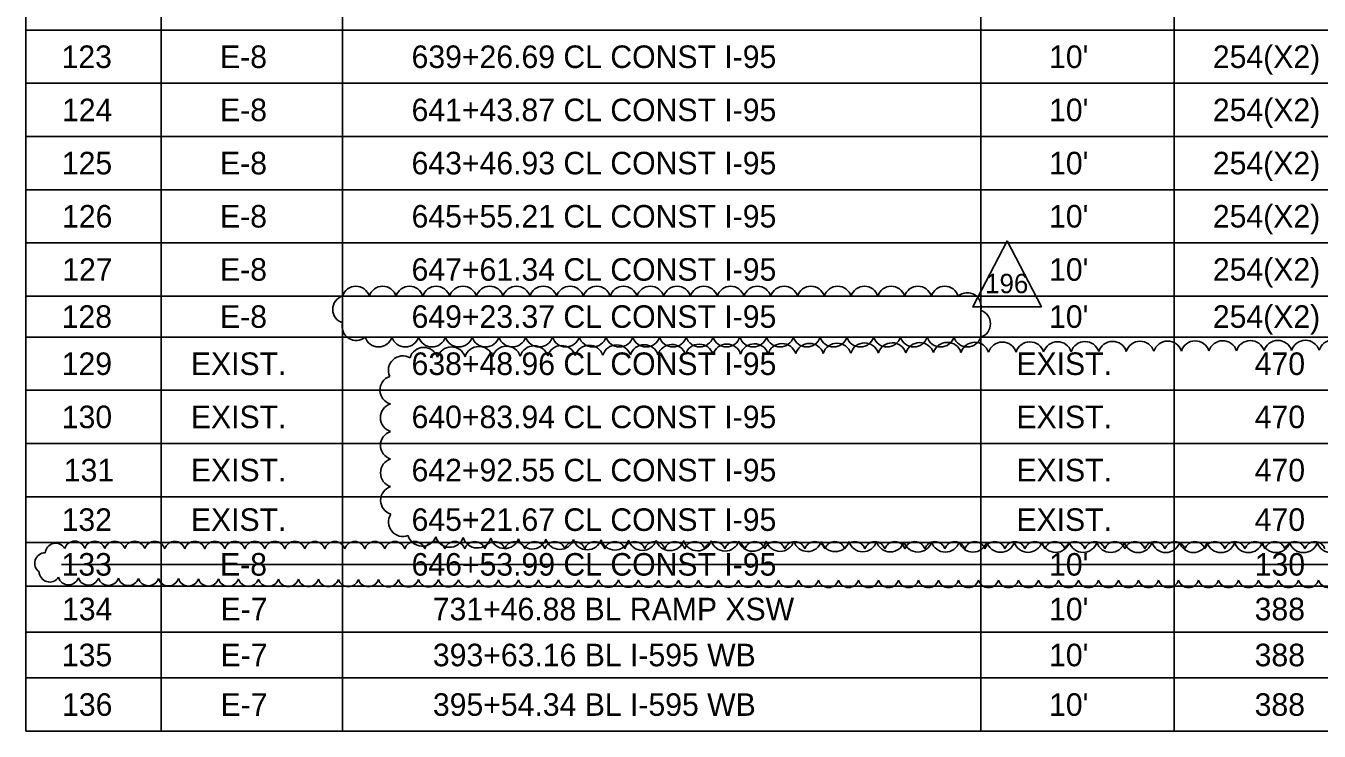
# Model space of a CAD drawing. Extents: x -818.1 to -802.4, y -2221.2 to -2187.7.
# Drawn here: x -817.208 to -813.196, y -2206.269 to -2204.081 of the extents above; entities that cross this region are included whole.
import ezdxf

# ---------------------------------------------------------------- set-up
doc = ezdxf.new("R2010")
doc.units = 0
for name, color, linetype in [('Cloud_dp', 7, 'Continuous'), ('SumBoxBorder_dp', 7, 'Continuous'), ('SumBoxLines_dp', 7, 'Continuous'), ('SumBoxLinesMin_dp', 7, 'Continuous'), ('TextLabel', 7, 'Continuous')]:
    doc.layers.add(name, color=color, linetype=linetype)

msp = doc.modelspace()

# ---------------------------------------------------------------- linework, layer by layer
at = {"layer": 'Cloud_dp'}
msp.add_line((-817.0974, -2205.7517), (-809.7376, -2205.7517), dxfattribs=at)
msp.add_lwpolyline([(-814.1639, -2204.7479), (-814.2705, -2204.9531), (-814.0574, -2204.9531)], close=True, dxfattribs=at)
for centre, radius, start, end in [((-816.1842, -2204.9322), 0.0435, 17.5, 162.5), ((-816.1011, -2204.9322), 0.0435, 17.5, 162.5), ((-816.0181, -2204.9322), 0.0435, 17.5, 162.5), ((-815.935, -2204.9322), 0.0435, 17.5, 162.5), ((-815.852, -2204.9322), 0.0435, 17.5, 162.5), ((-815.769, -2204.9322), 0.0435, 17.5, 162.5), ((-815.6859, -2204.9322), 0.0435, 17.5, 162.5), ((-815.6029, -2204.9322), 0.0435, 17.5, 162.5), ((-815.5199, -2204.9322), 0.0435, 17.5, 162.5), ((-815.4368, -2204.9322), 0.0435, 17.5, 162.5), ((-815.3538, -2204.9322), 0.0435, 17.5, 162.5), ((-815.2707, -2204.9322), 0.0435, 17.5, 162.5), ((-815.1877, -2204.9322), 0.0435, 17.5, 162.5), ((-815.1047, -2204.9322), 0.0435, 17.5, 162.5), ((-815.0216, -2204.9322), 0.0435, 17.5, 162.5), ((-814.9386, -2204.9322), 0.0435, 17.5, 162.5), ((-814.8555, -2204.9322), 0.0435, 17.5, 162.5), ((-814.7725, -2204.9322), 0.0435, 17.5, 162.5), ((-814.6895, -2204.9322), 0.0435, 17.5, 162.5), ((-814.6064, -2204.9322), 0.0435, 17.5, 162.5), ((-814.5234, -2204.9322), 0.0435, 17.5, 162.5), ((-814.4404, -2204.9322), 0.0435, 17.5, 162.5), ((-814.3573, -2204.9322), 0.0435, 17.5, 162.5), ((-816.2126, -2204.9607), 0.0435, 107.5, 252.5), ((-814.2877, -2204.9524), 0.0435, 345.1202, 130.1202), ((-814.2588, -2205.0051), 0.0435, 287.5, 72.5), ((-816.1836, -2205.0134), 0.0435, 165.1202, 310.1202), ((-816.114, -2205.0336), 0.0435, 197.5, 342.5), ((-816.031, -2205.0336), 0.0435, 197.5, 342.5), ((-815.948, -2205.0336), 0.0435, 197.5, 342.5), ((-815.8649, -2205.0336), 0.0435, 197.5, 342.5), ((-815.7819, -2205.0336), 0.0435, 197.5, 342.5), ((-815.6989, -2205.0336), 0.0435, 197.5, 342.5), ((-815.6158, -2205.0336), 0.0435, 197.5, 342.5), ((-815.5328, -2205.0336), 0.0435, 197.5, 342.5), ((-815.4497, -2205.0336), 0.0435, 197.5, 342.5), ((-815.3667, -2205.0336), 0.0435, 197.5, 342.5), ((-815.2837, -2205.0336), 0.0435, 197.5, 342.5), ((-815.2006, -2205.0336), 0.0435, 197.5, 342.5), ((-815.1176, -2205.0336), 0.0435, 197.5, 342.5), ((-815.0345, -2205.0336), 0.0435, 197.5, 342.5), ((-814.9515, -2205.0336), 0.0435, 197.5, 342.5), ((-814.8685, -2205.0336), 0.0435, 197.5, 342.5), ((-814.7854, -2205.0336), 0.0435, 197.5, 342.5), ((-814.7024, -2205.0336), 0.0435, 197.5, 342.5), ((-814.6194, -2205.0336), 0.0435, 197.5, 342.5), ((-814.5363, -2205.0336), 0.0435, 197.5, 342.5), ((-814.4533, -2205.0336), 0.0435, 197.5, 342.5), ((-814.3702, -2205.0336), 0.0435, 197.5, 342.5), ((-814.2872, -2205.0336), 0.0435, 197.5, 342.5), ((-815.9733, -2205.1234), 0.0448, 18.7303, 163.7303), ((-815.8879, -2205.1218), 0.0448, 18.4349, 163.4349), ((-815.8025, -2205.1205), 0.0448, 18.2937, 163.2937), ((-815.717, -2205.1194), 0.0448, 18.2063, 163.2063), ((-815.6315, -2205.1184), 0.0448, 18.1454, 163.1454), ((-815.5461, -2205.1175), 0.0448, 18.0999, 163.0999), ((-815.4606, -2205.1166), 0.0448, 18.0641, 163.0641), ((-815.3752, -2205.1158), 0.0448, 18.035, 163.035), ((-815.2897, -2205.115), 0.0448, 18.0108, 163.0108), ((-815.2042, -2205.1143), 0.0448, 17.9902, 162.9902), ((-815.1188, -2205.1135), 0.0448, 17.9724, 162.9724), ((-815.0333, -2205.1129), 0.0448, 17.9568, 162.9568), ((-814.9478, -2205.1122), 0.0448, 17.9431, 162.9431), ((-814.8623, -2205.1115), 0.0448, 17.9308, 162.9308), ((-814.7769, -2205.1109), 0.0448, 17.9197, 162.9197), ((-814.6914, -2205.1103), 0.0448, 17.9097, 162.9097), ((-814.6059, -2205.1097), 0.0448, 17.9005, 162.9005), ((-814.5205, -2205.1091), 0.0448, 17.8922, 162.8922), ((-814.435, -2205.1085), 0.0448, 17.8844, 162.8844), ((-814.3495, -2205.1079), 0.0448, 17.8773, 162.8773), ((-814.264, -2205.1074), 0.0448, 17.8707, 162.8707), ((-814.1786, -2205.1068), 0.0448, 17.8645, 162.8645), ((-814.0931, -2205.1063), 0.0448, 17.8587, 162.8587), ((-814.0076, -2205.1058), 0.0448, 17.8533, 162.8533), ((-813.9222, -2205.1052), 0.0448, 17.8482, 162.8482), ((-813.8367, -2205.1047), 0.0448, 17.8434, 162.8434), ((-813.7512, -2205.1042), 0.0448, 17.8389, 162.8389), ((-813.6657, -2205.1037), 0.0448, 17.8346, 162.8346), ((-813.5803, -2205.1032), 0.0448, 17.8305, 162.8305), ((-813.4948, -2205.1027), 0.0448, 17.8266, 162.8266), ((-813.4093, -2205.1022), 0.0448, 17.823, 162.823), ((-813.3238, -2205.1018), 0.0448, 17.8195, 162.8195), ((-813.2384, -2205.1013), 0.0448, 17.8161, 162.8161), ((-813.1529, -2205.1008), 0.0448, 17.8129, 162.8129), ((-816.0387, -2205.1497), 0.0448, 59.9612, 204.9612), ((-816.0648, -2205.211), 0.0448, 108.8776, 253.8776), ((-816.0635, -2205.2967), 0.0448, 107.8667, 252.8667), ((-816.0632, -2205.3822), 0.0448, 107.5797, 252.5797), ((-816.0631, -2205.4677), 0.0448, 107.5929, 252.5929), ((-816.0627, -2205.5531), 0.0448, 107.8913, 252.8913), ((-816.0385, -2205.6205), 0.0448, 146.7173, 291.7173), ((-817.1157, -2205.7187), 0.0325, 30.0061, 175.0061), ((-817.0566, -2205.7123), 0.0325, 17.2993, 162.2993), ((-816.9945, -2205.7125), 0.0325, 17.3718, 162.3718), ((-816.9324, -2205.7126), 0.0325, 17.4014, 162.4014), ((-816.8704, -2205.7127), 0.0325, 17.4187, 162.4187), ((-816.8083, -2205.7128), 0.0325, 17.4304, 162.4304), ((-816.7462, -2205.7128), 0.0325, 17.4391, 162.4391), ((-816.6842, -2205.7129), 0.0325, 17.4458, 162.4458), ((-816.6221, -2205.7129), 0.0325, 17.4511, 162.4511), ((-816.5601, -2205.713), 0.0325, 17.4556, 162.4556), ((-816.498, -2205.713), 0.0325, 17.4594, 162.4594), ((-816.4359, -2205.7131), 0.0325, 17.4626, 162.4626), ((-816.3739, -2205.7131), 0.0325, 17.4654, 162.4654), ((-816.3118, -2205.7132), 0.0325, 17.4679, 162.4679), ((-816.2498, -2205.7132), 0.0325, 17.4701, 162.4701), ((-816.1877, -2205.7132), 0.0325, 17.4721, 162.4721), ((-816.1257, -2205.7133), 0.0325, 17.4739, 162.4739), ((-816.0636, -2205.7133), 0.0325, 17.4756, 162.4756), ((-816.0015, -2205.7133), 0.0325, 17.4771, 162.4771), ((-815.9786, -2205.6506), 0.0448, 194.8595, 339.8595), ((-815.9395, -2205.7133), 0.0325, 17.4784, 162.4784), ((-815.8934, -2205.6539), 0.0448, 195.7789, 340.7789), ((-815.8774, -2205.7133), 0.0325, 17.4797, 162.4797), ((-815.808, -2205.6561), 0.0448, 196.1857, 341.1857), ((-815.8154, -2205.7134), 0.0325, 17.4809, 162.4809), ((-815.7533, -2205.7134), 0.0325, 17.482, 162.482), ((-815.7226, -2205.6579), 0.0448, 196.4302, 341.4302), ((-815.6912, -2205.7134), 0.0325, 17.483, 162.483), ((-815.6372, -2205.6594), 0.0448, 196.598, 341.598), ((-815.6292, -2205.7134), 0.0325, 17.484, 162.484), ((-815.5671, -2205.7134), 0.0325, 17.4849, 162.4849), ((-815.5517, -2205.6606), 0.0448, 196.7224, 341.7224), ((-815.5051, -2205.7135), 0.0325, 17.4858, 162.4858), ((-815.4663, -2205.6617), 0.0448, 196.8195, 341.8195), ((-815.443, -2205.7135), 0.0325, 17.4866, 162.4866), ((-815.3809, -2205.6627), 0.0448, 196.8979, 341.8979), ((-815.3809, -2205.7135), 0.0325, 17.4873, 162.4873), ((-815.3189, -2205.7135), 0.0325, 17.488, 162.488), ((-815.2954, -2205.6635), 0.0448, 196.963, 341.963), ((-815.2568, -2205.7135), 0.0325, 17.4887, 162.4887), ((-815.2099, -2205.6643), 0.0448, 197.0182, 342.0182), ((-815.1948, -2205.7135), 0.0325, 17.4894, 162.4894), ((-815.1245, -2205.665), 0.0448, 197.0657, 342.0657), ((-815.1327, -2205.7135), 0.0325, 17.49, 162.49), ((-815.0707, -2205.7135), 0.0325, 17.4906, 162.4906), ((-815.039, -2205.6656), 0.0448, 197.1072, 342.1072), ((-815.0086, -2205.7136), 0.0325, 17.4912, 162.4912), ((-814.9535, -2205.6662), 0.0448, 197.1439, 342.1439), ((-814.9465, -2205.7136), 0.0325, 17.4917, 162.4917), ((-814.8845, -2205.7136), 0.0325, 17.4922, 162.4922), ((-814.8681, -2205.6667), 0.0448, 197.1765, 342.1765), ((-814.8224, -2205.7136), 0.0325, 17.4927, 162.4927), ((-814.7826, -2205.6671), 0.0448, 197.2059, 342.2059), ((-814.7604, -2205.7136), 0.0325, 17.4932, 162.4932), ((-814.6971, -2205.6675), 0.0448, 197.2325, 342.2325), ((-814.6983, -2205.7136), 0.0325, 17.4936, 162.4936), ((-814.6362, -2205.7136), 0.0325, 17.4941, 162.4941), ((-814.6117, -2205.6679), 0.0448, 197.2567, 342.2567), ((-814.5742, -2205.7136), 0.0325, 17.4945, 162.4945), ((-814.5262, -2205.6683), 0.0448, 197.2789, 342.2789), ((-814.5121, -2205.7136), 0.0325, 17.4949, 162.4949), ((-814.4407, -2205.6686), 0.0448, 197.2994, 342.2994), ((-814.4501, -2205.7136), 0.0325, 17.4953, 162.4953), ((-814.388, -2205.7136), 0.0325, 17.4957, 162.4957), ((-814.3553, -2205.6689), 0.0448, 197.3182, 342.3182), ((-814.326, -2205.7136), 0.0325, 17.4961, 162.4961), ((-814.2698, -2205.6691), 0.0448, 197.3358, 342.3358), ((-814.2639, -2205.7136), 0.0325, 17.4964, 162.4964), ((-814.2018, -2205.7136), 0.0325, 17.4968, 162.4968), ((-814.1843, -2205.6694), 0.0448, 197.3521, 342.3521), ((-814.1398, -2205.7136), 0.0325, 17.4971, 162.4971), ((-814.0989, -2205.6696), 0.0448, 197.3673, 342.3673), ((-814.0777, -2205.7136), 0.0325, 17.4974, 162.4974), ((-814.0134, -2205.6698), 0.0448, 197.3816, 342.3816), ((-814.0157, -2205.7136), 0.0325, 17.4978, 162.4978), ((-813.9536, -2205.7137), 0.0325, 17.4981, 162.4981), ((-813.9279, -2205.6699), 0.0448, 197.395, 342.395), ((-813.8915, -2205.7137), 0.0325, 17.4984, 162.4984), ((-813.8424, -2205.6701), 0.0448, 197.4077, 342.4077), ((-813.8295, -2205.7137), 0.0325, 17.4986, 162.4986), ((-813.757, -2205.6702), 0.0448, 197.4196, 342.4196), ((-813.7674, -2205.7137), 0.0325, 17.4989, 162.4989), ((-813.7054, -2205.7137), 0.0325, 17.4992, 162.4992), ((-813.6715, -2205.6703), 0.0448, 197.4309, 342.4309), ((-813.6433, -2205.7137), 0.0325, 17.4995, 162.4995), ((-813.586, -2205.6704), 0.0448, 197.4416, 342.4416), ((-813.5812, -2205.7137), 0.0325, 17.4997, 162.4997), ((-813.5192, -2205.7137), 0.0325, 17.4998, 162.4998), ((-813.5005, -2205.6705), 0.0448, 197.4518, 342.4518), ((-813.4571, -2205.7137), 0.0325, 17.4986, 162.4986), ((-813.4151, -2205.6706), 0.0448, 197.4615, 342.4615), ((-813.3951, -2205.7137), 0.0325, 17.497, 162.497), ((-813.3296, -2205.6706), 0.0448, 197.4707, 342.4707), ((-813.333, -2205.7137), 0.0325, 17.4953, 162.4953), ((-813.271, -2205.7137), 0.0325, 17.4935, 162.4935), ((-813.2441, -2205.6706), 0.0448, 197.4795, 342.4795), ((-813.2089, -2205.7137), 0.0325, 17.4918, 162.4918), ((-813.1586, -2205.6707), 0.0448, 197.4879, 342.4879), ((-817.1482, -2205.7483), 0.0325, 89.8591, 234.8591), ((-817.1344, -2205.774), 0.0326, 181.6179, 326.6179), ((-817.076, -2205.7828), 0.0325, 196.2837, 341.2837), ((-817.014, -2205.7839), 0.0325, 196.7139, 341.7139), ((-816.952, -2205.7846), 0.0325, 196.8932, 341.8932), ((-816.8899, -2205.7852), 0.0325, 196.9988, 341.9988), ((-816.8279, -2205.7857), 0.0325, 197.0706, 342.0706), ((-816.7658, -2205.7861), 0.0325, 197.1234, 342.1234), ((-816.7038, -2205.7865), 0.0325, 197.1645, 342.1645), ((-816.6417, -2205.7869), 0.0325, 197.1975, 342.1975), ((-816.5797, -2205.7872), 0.0325, 197.2249, 342.2249), ((-816.5176, -2205.7875), 0.0325, 197.2481, 342.2481), ((-816.4556, -2205.7877), 0.0325, 197.268, 342.268), ((-816.3935, -2205.788), 0.0325, 197.2853, 342.2853), ((-816.3315, -2205.7882), 0.0325, 197.3007, 342.3007), ((-816.2694, -2205.7884), 0.0325, 197.3143, 342.3143), ((-816.2074, -2205.7886), 0.0325, 197.3266, 342.3266), ((-816.1453, -2205.7888), 0.0325, 197.3377, 342.3377), ((-816.0832, -2205.789), 0.0325, 197.3478, 342.3478), ((-816.0212, -2205.7891), 0.0325, 197.357, 342.357), ((-815.9591, -2205.7893), 0.0325, 197.3655, 342.3655), ((-815.8971, -2205.7894), 0.0325, 197.3734, 342.3734), ((-815.835, -2205.7895), 0.0325, 197.3807, 342.3807), ((-815.773, -2205.7897), 0.0325, 197.3875, 342.3875), ((-815.7109, -2205.7898), 0.0325, 197.3938, 342.3938), ((-815.6488, -2205.7899), 0.0325, 197.3998, 342.3998), ((-815.5868, -2205.79), 0.0325, 197.4053, 342.4053), ((-815.5247, -2205.7901), 0.0325, 197.4106, 342.4106), ((-815.4627, -2205.7902), 0.0325, 197.4155, 342.4155), ((-815.4006, -2205.7903), 0.0325, 197.4202, 342.4202), ((-815.3386, -2205.7904), 0.0325, 197.4247, 342.4247), ((-815.2765, -2205.7905), 0.0325, 197.4289, 342.4289), ((-815.2144, -2205.7905), 0.0325, 197.4329, 342.4329), ((-815.1524, -2205.7906), 0.0325, 197.4368, 342.4368), ((-815.0903, -2205.7907), 0.0325, 197.4404, 342.4404), ((-815.0283, -2205.7907), 0.0325, 197.4439, 342.4439), ((-814.9662, -2205.7908), 0.0325, 197.4472, 342.4472), ((-814.9041, -2205.7908), 0.0325, 197.4504, 342.4504), ((-814.8421, -2205.7909), 0.0325, 197.4535, 342.4535), ((-814.78, -2205.7909), 0.0325, 197.4565, 342.4565), ((-814.718, -2205.791), 0.0325, 197.4593, 342.4593), ((-814.6559, -2205.791), 0.0325, 197.462, 342.462), ((-814.5939, -2205.7911), 0.0325, 197.4646, 342.4646), ((-814.5318, -2205.7911), 0.0325, 197.4672, 342.4672), ((-814.4697, -2205.7911), 0.0325, 197.4696, 342.4696), ((-814.4077, -2205.7912), 0.0325, 197.472, 342.472), ((-814.3456, -2205.7912), 0.0325, 197.4742, 342.4742), ((-814.2836, -2205.7912), 0.0325, 197.4765, 342.4765), ((-814.2215, -2205.7913), 0.0325, 197.4786, 342.4786), ((-814.1594, -2205.7913), 0.0325, 197.4807, 342.4807), ((-814.0974, -2205.7913), 0.0325, 197.4827, 342.4827), ((-814.0353, -2205.7913), 0.0325, 197.4846, 342.4846), ((-813.9733, -2205.7913), 0.0325, 197.4865, 342.4865), ((-813.9112, -2205.7913), 0.0325, 197.4883, 342.4883), ((-813.8492, -2205.7914), 0.0325, 197.4901, 342.4901), ((-813.7871, -2205.7914), 0.0325, 197.4918, 342.4918), ((-813.725, -2205.7914), 0.0325, 197.4935, 342.4935), ((-813.663, -2205.7914), 0.0325, 197.4951, 342.4951), ((-813.6009, -2205.7914), 0.0325, 197.4967, 342.4967), ((-813.5389, -2205.7914), 0.0325, 197.4983, 342.4983), ((-813.4768, -2205.7914), 0.0325, 197.4998, 342.4998), ((-813.4148, -2205.7914), 0.0325, 197.5012, 342.5012), ((-813.3527, -2205.7914), 0.0325, 197.5025, 342.5025), ((-813.2906, -2205.7914), 0.0325, 197.5039, 342.5039), ((-813.2286, -2205.7914), 0.0325, 197.5054, 342.5054), ((-813.1665, -2205.7914), 0.0325, 197.5069, 342.5069)]:
    msp.add_arc(centre, radius, start, end, dxfattribs=at)
at = {"layer": 'SumBoxBorder_dp'}
for p, q in [((-817.2082, -2199.4742), (-817.2082, -2206.2692)), ((-817.2082, -2206.2692), (-811.1482, -2206.2692))]:
    msp.add_line(p, q, dxfattribs=at)
at = {"layer": 'SumBoxLines_dp'}
for p, q in [((-816.7882, -2199.8042), (-816.7882, -2206.2692)), ((-816.7882, -2199.8042), (-816.7882, -2206.2692)), ((-816.2257, -2199.8042), (-816.2257, -2206.2692)), ((-816.2257, -2199.8042), (-816.2257, -2206.2692)), ((-814.2457, -2199.8042), (-814.2457, -2206.2692)), ((-814.2457, -2199.8042), (-814.2457, -2206.2692)), ((-813.6457, -2199.8042), (-813.6457, -2206.2692)), ((-813.6457, -2199.8042), (-813.6457, -2206.2692))]:
    msp.add_line(p, q, dxfattribs=at)
at = {"layer": 'SumBoxLinesMin_dp'}
for p, q in [((-817.2082, -2204.0942), (-809.6857, -2204.0942)), ((-817.2082, -2204.0942), (-809.6857, -2204.0942)), ((-817.2082, -2204.2592), (-809.6857, -2204.2592)), ((-817.2082, -2204.2592), (-809.6857, -2204.2592)), ((-817.2082, -2204.4242), (-809.6857, -2204.4242)), ((-817.2082, -2204.4242), (-809.6857, -2204.4242)), ((-817.2082, -2204.5892), (-809.6857, -2204.5892)), ((-817.2082, -2204.5892), (-809.6857, -2204.5892)), ((-817.2082, -2204.7542), (-809.6857, -2204.7542)), ((-817.2082, -2204.7542), (-809.6857, -2204.7542)), ((-817.2082, -2204.9192), (-816.7882, -2204.9192)), ((-817.2082, -2204.9192), (-809.6857, -2204.9192)), ((-816.2257, -2204.9192), (-809.6857, -2204.9192)), ((-817.2082, -2205.0467), (-809.6857, -2205.0467)), ((-817.2082, -2205.0467), (-809.6857, -2205.0467)), ((-817.2082, -2205.2117), (-816.2257, -2205.2117)), ((-817.2082, -2205.2117), (-809.6857, -2205.2117)), ((-814.2457, -2205.2117), (-809.6857, -2205.2117)), ((-817.2082, -2205.3767), (-813.6457, -2205.3767)), ((-817.2082, -2205.3767), (-809.6857, -2205.3767)), ((-817.2082, -2205.5417), (-816.7882, -2205.5417)), ((-817.2082, -2205.5417), (-809.6857, -2205.5417)), ((-814.2457, -2205.5417), (-809.6857, -2205.5417)), ((-817.2082, -2205.6842), (-816.2257, -2205.6842)), ((-817.2082, -2205.6842), (-809.6857, -2205.6842)), ((-814.2457, -2205.6842), (-813.6457, -2205.6842)), ((-817.2082, -2205.8192), (-809.6857, -2205.8192)), ((-816.7882, -2205.8192), (-811.1482, -2205.8192)), ((-817.2082, -2205.9617), (-816.7882, -2205.9617)), ((-817.2082, -2205.9617), (-809.6857, -2205.9617)), ((-816.2257, -2205.9617), (-814.2457, -2205.9617)), ((-817.2082, -2206.1042), (-809.6857, -2206.1042)), ((-816.7882, -2206.1042), (-816.2257, -2206.1042)), ((-813.6457, -2206.1042), (-811.1482, -2206.1042))]:
    msp.add_line(p, q, dxfattribs=at)

# ---------------------------------------------------------------- texts
at = {"layer": 'Cloud_dp'}
msp.add_text('196', height=0.06, dxfattribs=at).set_placement((-814.2319, -2204.9103))
at = {"layer": 'TextLabel'}
for s, p in [('123', (-817.0974, -2204.2117)), ('E-8', (-816.6058, -2204.2117)), ('639+26.69 CL CONST I-95', (-816.0115, -2204.2117)), ("10'", (-814.0336, -2204.2117)), ('254(X2)', (-813.5254, -2204.2117)), ('124', (-817.096, -2204.3767)), ('E-8', (-816.6058, -2204.3767)), ('641+43.87 CL CONST I-95', (-816.0115, -2204.3767)), ("10'", (-814.0336, -2204.3767)), ('254(X2)', (-813.5254, -2204.3767)), ('125', (-817.0965, -2204.5417)), ('E-8', (-816.6058, -2204.5417)), ('643+46.93 CL CONST I-95', (-816.0115, -2204.5417)), ("10'", (-814.0336, -2204.5417)), ('254(X2)', (-813.5254, -2204.5417)), ('126', (-817.0959, -2204.7067)), ('E-8', (-816.6058, -2204.7067)), ('645+55.21 CL CONST I-95', (-816.0115, -2204.7067)), ("10'", (-814.0336, -2204.7067)), ('254(X2)', (-813.5254, -2204.7067)), ('127', (-817.0953, -2204.8717)), ('E-8', (-816.6058, -2204.8717)), ('647+61.34 CL CONST I-95', (-816.0115, -2204.8717)), ("10'", (-814.0336, -2204.8717)), ('254(X2)', (-813.5254, -2204.8717)), ('128', (-817.0971, -2205.0179)), ('E-8', (-816.6058, -2205.0179)), ('649+23.37 CL CONST I-95', (-816.0115, -2205.0179)), ("10'", (-814.0336, -2205.0179)), ('254(X2)', (-813.5254, -2205.0179)), ('129', (-817.097, -2205.1642)), ('EXIST.', (-816.6962, -2205.1642)), ('638+48.96 CL CONST I-95', (-816.0115, -2205.1642)), ('EXIST.', (-814.135, -2205.1642)), ('470', (-813.3955, -2205.1642)), ('130', (-817.0968, -2205.3292)), ('EXIST.', (-816.6962, -2205.3292)), ('640+83.94 CL CONST I-95', (-816.0115, -2205.3292)), ('EXIST.', (-814.135, -2205.3292)), ('470', (-813.3955, -2205.3292)), ('131', (-817.0906, -2205.4942)), ('EXIST.', (-816.6962, -2205.4942)), ('642+92.55 CL CONST I-95', (-816.0115, -2205.4942)), ('EXIST.', (-814.135, -2205.4942)), ('470', (-813.3955, -2205.4942)), ('132', (-817.0973, -2205.6479)), ('EXIST.', (-816.6962, -2205.6479)), ('645+21.67 CL CONST I-95', (-816.0115, -2205.6479)), ('EXIST.', (-814.135, -2205.6479)), ('470', (-813.3955, -2205.6479)), ('133', (-817.0974, -2205.7867)), ('E-8', (-816.6058, -2205.7867)), ('646+53.99 CL CONST I-95', (-816.0115, -2205.7867)), ("10'", (-814.0336, -2205.7867)), ('130', (-813.3955, -2205.7867)), ('134', (-817.096, -2205.9254)), ('E-7', (-816.6041, -2205.9254)), ('731+46.88 BL RAMP XSW', (-815.9458, -2205.9254)), ("10'", (-814.0336, -2205.9254)), ('388', (-813.3958, -2205.9254)), ('135', (-817.0965, -2206.0679)), ('E-7', (-816.6041, -2206.0679)), ('393+63.16 BL I-595 WB', (-815.9453, -2206.0679)), ("10'", (-814.0336, -2206.0679)), ('388', (-813.3958, -2206.0679)), ('136', (-817.0959, -2206.2217)), ('E-7', (-816.6041, -2206.2217)), ('395+54.34 BL I-595 WB', (-815.9453, -2206.2217)), ("10'", (-814.0336, -2206.2217)), ('388', (-813.3958, -2206.2217))]:
    msp.add_text(s, height=0.07, dxfattribs=at).set_placement(p)

doc.saveas('drawing.dxf')
